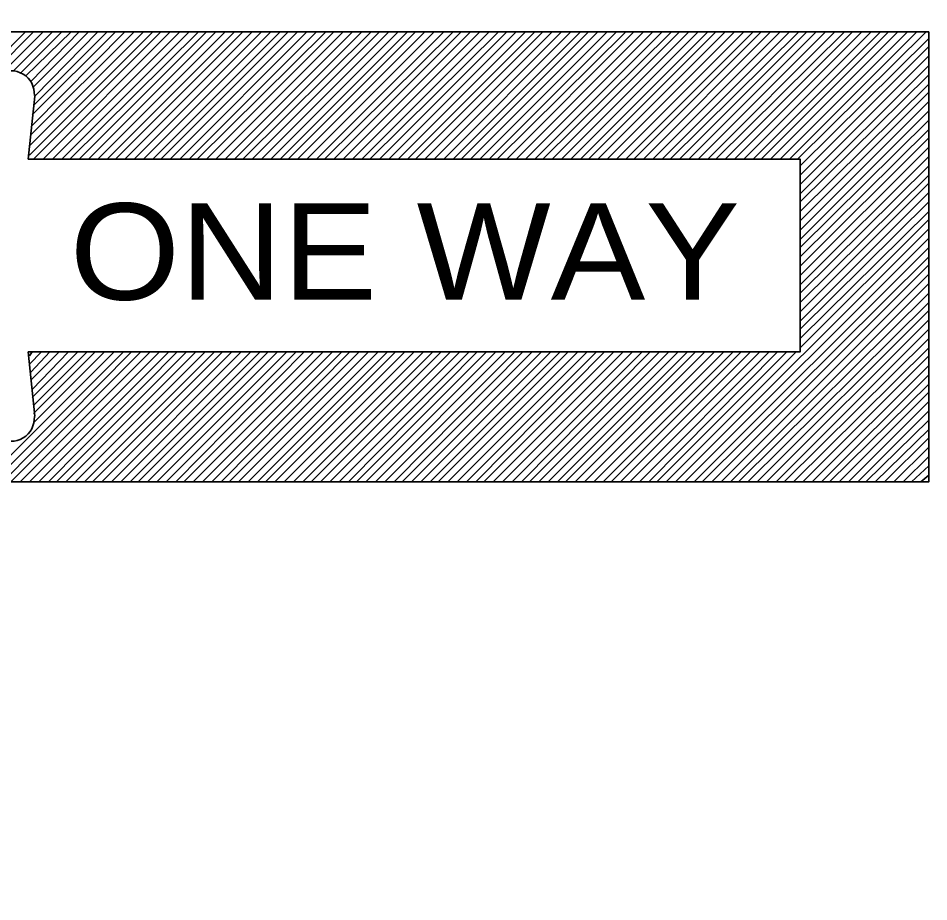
# Model space of a CAD drawing. Extents: x -198 to 658, y -402 to 142.
# Drawn here: x 497.03 to 513.34, y -95.51 to -79.68 of the extents above; entities that cross this region are included whole.
import ezdxf
from ezdxf.enums import TextEntityAlignment as Align

# ---------------------------------------------------------------- set-up
doc = ezdxf.new("R2010")
doc.units = 0
doc.header["$LTSCALE"] = 0.96
doc.layers.add('1', color=7, linetype='Continuous', lineweight=35)

msp = doc.modelspace()

# ---------------------------------------------------------------- linework, layer by layer
at = {"layer": '1'}
for p, q in [((491.4509, -85.6372), (497.1629, -79.9252)), ((491.4509, -85.8052), (497.3069, -79.9252)), ((491.4509, -85.6372), (497.1629, -79.9252)), ((491.4509, -85.8052), (497.3069, -79.9252)), ((496.7549, -80.6452), (497.4749, -79.9252)), ((496.7549, -80.6452), (497.4749, -79.9252)), ((496.9469, -80.6212), (497.6429, -79.9252)), ((496.9469, -80.6212), (497.6429, -79.9252)), ((497.0669, -80.6692), (497.8109, -79.9252)), ((497.0669, -80.6692), (497.8109, -79.9252)), ((497.1629, -80.7172), (497.9789, -79.9252)), ((497.1629, -80.7172), (497.9789, -79.9252)), ((497.2349, -81.9652), (499.2749, -79.9252)), ((497.2349, -82.1332), (499.4429, -79.9252)), ((497.2349, -81.9652), (499.2749, -79.9252)), ((497.2349, -82.1332), (499.4429, -79.9252)), ((497.2589, -80.8132), (498.1229, -79.9252)), ((497.2589, -81.7732), (499.1069, -79.9252)), ((497.2589, -80.8132), (498.1229, -79.9252)), ((497.2589, -81.7732), (499.1069, -79.9252)), ((497.2829, -81.4132), (498.7709, -79.9252)), ((497.2829, -81.6052), (498.9389, -79.9252)), ((497.2829, -81.4132), (498.7709, -79.9252)), ((497.2829, -81.6052), (498.9389, -79.9252)), ((497.3069, -80.9092), (498.2909, -79.9252)), ((497.3069, -81.2452), (498.6269, -79.9252)), ((497.3069, -82.2052), (499.5869, -79.9252)), ((497.3069, -80.9092), (498.2909, -79.9252)), ((497.3069, -81.2452), (498.6269, -79.9252)), ((497.3069, -82.2052), (499.5869, -79.9252)), ((497.3309, -81.0772), (498.4589, -79.9252)), ((497.3309, -81.0772), (498.4589, -79.9252)), ((497.4749, -82.2052), (499.7549, -79.9252)), ((497.4749, -82.2052), (499.7549, -79.9252)), ((497.6429, -82.2052), (499.9229, -79.9252)), ((497.6429, -82.2052), (499.9229, -79.9252)), ((497.8109, -82.2052), (500.0909, -79.9252)), ((497.8109, -82.2052), (500.0909, -79.9252)), ((497.9549, -82.2052), (500.2589, -79.9252)), ((497.9549, -82.2052), (500.2589, -79.9252)), ((498.1229, -82.2052), (500.4029, -79.9252)), ((498.1229, -82.2052), (500.4029, -79.9252)), ((498.2909, -82.2052), (500.5709, -79.9252)), ((498.2909, -82.2052), (500.5709, -79.9252)), ((498.4589, -82.2052), (500.7389, -79.9252)), ((498.4589, -82.2052), (500.7389, -79.9252)), ((498.6269, -82.2052), (500.9069, -79.9252)), ((498.6269, -82.2052), (500.9069, -79.9252)), ((498.7709, -82.2052), (501.0509, -79.9252)), ((498.7709, -82.2052), (501.0509, -79.9252)), ((498.9389, -82.2052), (501.2189, -79.9252)), ((498.9389, -82.2052), (501.2189, -79.9252)), ((499.1069, -82.2052), (501.3869, -79.9252)), ((499.1069, -82.2052), (501.3869, -79.9252)), ((499.2749, -82.2052), (501.5549, -79.9252)), ((499.2749, -82.2052), (501.5549, -79.9252)), ((499.4429, -82.2052), (501.7229, -79.9252)), ((499.4429, -82.2052), (501.7229, -79.9252)), ((499.5869, -82.2052), (501.8669, -79.9252)), ((499.5869, -82.2052), (501.8669, -79.9252)), ((499.7549, -82.2052), (502.0349, -79.9252)), ((499.7549, -82.2052), (502.0349, -79.9252)), ((499.9229, -82.2052), (502.2029, -79.9252)), ((499.9229, -82.2052), (502.2029, -79.9252)), ((500.0909, -82.2052), (502.3709, -79.9252)), ((500.0909, -82.2052), (502.3709, -79.9252)), ((500.2349, -82.2052), (502.5389, -79.9252)), ((500.2349, -82.2052), (502.5389, -79.9252)), ((500.4029, -82.2052), (502.6829, -79.9252)), ((500.4029, -82.2052), (502.6829, -79.9252)), ((500.5709, -82.2052), (502.8509, -79.9252)), ((500.5709, -82.2052), (502.8509, -79.9252)), ((500.7389, -82.2052), (503.0189, -79.9252)), ((500.7389, -82.2052), (503.0189, -79.9252)), ((500.9069, -82.2052), (503.1869, -79.9252)), ((500.9069, -82.2052), (503.1869, -79.9252)), ((501.0509, -82.2052), (503.3549, -79.9252)), ((501.0509, -82.2052), (503.3549, -79.9252)), ((501.2189, -82.2052), (503.4989, -79.9252)), ((501.2189, -82.2052), (503.4989, -79.9252)), ((501.3869, -82.2052), (503.6669, -79.9252)), ((501.3869, -82.2052), (503.6669, -79.9252)), ((501.5549, -82.2052), (503.8349, -79.9252)), ((501.5549, -82.2052), (503.8349, -79.9252)), ((501.7229, -82.2052), (504.0029, -79.9252)), ((501.7229, -82.2052), (504.0029, -79.9252)), ((501.8669, -82.2052), (504.1469, -79.9252)), ((501.8669, -82.2052), (504.1469, -79.9252)), ((502.0349, -82.2052), (504.3149, -79.9252)), ((502.0349, -82.2052), (504.3149, -79.9252)), ((502.2029, -82.2052), (504.4829, -79.9252)), ((502.2029, -82.2052), (504.4829, -79.9252)), ((502.3709, -82.2052), (504.6509, -79.9252)), ((502.3709, -82.2052), (504.6509, -79.9252)), ((502.5149, -82.2052), (504.8189, -79.9252)), ((502.5149, -82.2052), (504.8189, -79.9252)), ((502.6829, -82.2052), (504.9629, -79.9252)), ((502.6829, -82.2052), (504.9629, -79.9252)), ((502.8509, -82.2052), (505.1309, -79.9252)), ((502.8509, -82.2052), (505.1309, -79.9252)), ((503.0189, -82.2052), (505.2989, -79.9252)), ((503.0189, -82.2052), (505.2989, -79.9252)), ((503.1869, -82.2052), (505.4669, -79.9252)), ((503.1869, -82.2052), (505.4669, -79.9252)), ((503.3309, -82.2052), (505.6349, -79.9252)), ((503.3309, -82.2052), (505.6349, -79.9252)), ((503.4989, -82.2052), (505.7789, -79.9252)), ((503.4989, -82.2052), (505.7789, -79.9252)), ((503.6669, -82.2052), (505.9469, -79.9252)), ((503.6669, -82.2052), (505.9469, -79.9252)), ((503.8349, -82.2052), (506.1149, -79.9252)), ((503.8349, -82.2052), (506.1149, -79.9252)), ((504.0029, -82.2052), (506.2829, -79.9252)), ((504.0029, -82.2052), (506.2829, -79.9252)), ((504.1469, -82.2052), (506.4269, -79.9252)), ((504.1469, -82.2052), (506.4269, -79.9252)), ((504.3149, -82.2052), (506.5949, -79.9252)), ((504.3149, -82.2052), (506.5949, -79.9252)), ((504.4829, -82.2052), (506.7629, -79.9252)), ((504.4829, -82.2052), (506.7629, -79.9252)), ((504.6509, -82.2052), (506.9309, -79.9252)), ((504.6509, -82.2052), (506.9309, -79.9252)), ((504.8189, -82.2052), (507.0989, -79.9252)), ((504.8189, -82.2052), (507.0989, -79.9252)), ((504.9629, -82.2052), (507.2429, -79.9252)), ((504.9629, -82.2052), (507.2429, -79.9252)), ((505.1309, -82.2052), (507.4109, -79.9252)), ((505.1309, -82.2052), (507.4109, -79.9252)), ((505.2989, -82.2052), (507.5789, -79.9252)), ((505.2989, -82.2052), (507.5789, -79.9252)), ((505.4669, -82.2052), (507.7469, -79.9252)), ((505.4669, -82.2052), (507.7469, -79.9252)), ((505.6109, -82.2052), (507.9149, -79.9252)), ((505.6109, -82.2052), (507.9149, -79.9252)), ((505.7789, -82.2052), (508.0589, -79.9252)), ((505.7789, -82.2052), (508.0589, -79.9252)), ((505.9469, -82.2052), (508.2269, -79.9252)), ((505.9469, -82.2052), (508.2269, -79.9252)), ((506.1149, -82.2052), (508.3949, -79.9252)), ((506.1149, -82.2052), (508.3949, -79.9252)), ((506.2829, -82.2052), (508.5629, -79.9252)), ((506.2829, -82.2052), (508.5629, -79.9252)), ((506.4269, -82.2052), (508.7309, -79.9252)), ((506.4269, -82.2052), (508.7309, -79.9252)), ((506.5949, -82.2052), (508.8749, -79.9252)), ((506.5949, -82.2052), (508.8749, -79.9252)), ((506.7629, -82.2052), (509.0429, -79.9252)), ((506.7629, -82.2052), (509.0429, -79.9252)), ((506.9309, -82.2052), (509.2109, -79.9252)), ((506.9309, -82.2052), (509.2109, -79.9252)), ((507.0989, -82.2052), (509.3789, -79.9252)), ((507.0989, -82.2052), (509.3789, -79.9252)), ((507.2429, -82.2052), (509.5229, -79.9252)), ((507.2429, -82.2052), (509.5229, -79.9252)), ((507.4109, -82.2052), (509.6909, -79.9252)), ((507.4109, -82.2052), (509.6909, -79.9252)), ((507.5789, -82.2052), (509.8589, -79.9252)), ((507.5789, -82.2052), (509.8589, -79.9252)), ((507.7469, -82.2052), (510.0269, -79.9252)), ((507.7469, -82.2052), (510.0269, -79.9252)), ((507.9149, -82.2052), (510.1949, -79.9252)), ((507.9149, -82.2052), (510.1949, -79.9252)), ((508.0589, -82.2052), (510.3389, -79.9252)), ((508.0589, -82.2052), (510.3389, -79.9252)), ((508.2269, -82.2052), (510.5069, -79.9252)), ((508.2269, -82.2052), (510.5069, -79.9252)), ((508.3949, -82.2052), (510.6749, -79.9252)), ((508.3949, -82.2052), (510.6749, -79.9252)), ((508.5629, -82.2052), (510.8429, -79.9252)), ((508.5629, -82.2052), (510.8429, -79.9252)), ((508.7069, -82.2052), (511.0109, -79.9252)), ((508.7069, -82.2052), (511.0109, -79.9252)), ((508.8749, -82.2052), (511.1549, -79.9252)), ((508.8749, -82.2052), (511.1549, -79.9252)), ((509.0429, -82.2052), (511.3229, -79.9252)), ((509.0429, -82.2052), (511.3229, -79.9252)), ((509.2109, -82.2052), (511.4909, -79.9252)), ((509.2109, -82.2052), (511.4909, -79.9252)), ((509.3789, -82.2052), (511.6589, -79.9252)), ((509.3789, -82.2052), (511.6589, -79.9252)), ((509.5229, -82.2052), (511.8269, -79.9252)), ((509.5229, -82.2052), (511.8269, -79.9252)), ((509.6909, -82.2052), (511.9709, -79.9252)), ((509.6909, -82.2052), (511.9709, -79.9252)), ((509.8589, -82.2052), (512.1389, -79.9252)), ((509.8589, -82.2052), (512.1389, -79.9252)), ((510.0269, -82.2052), (512.3069, -79.9252)), ((510.0269, -82.2052), (512.3069, -79.9252)), ((510.1949, -82.2052), (512.4749, -79.9252)), ((510.1949, -82.2052), (512.4749, -79.9252)), ((510.3389, -82.2052), (512.6189, -79.9252)), ((510.3389, -82.2052), (512.6189, -79.9252)), ((510.5069, -82.2052), (512.7869, -79.9252)), ((510.5069, -82.2052), (512.7869, -79.9252)), ((510.6749, -82.2052), (512.9549, -79.9252)), ((510.6749, -82.2052), (512.9549, -79.9252)), ((510.8429, -82.2052), (513.1229, -79.9252)), ((510.8429, -82.2052), (513.1229, -79.9252)), ((510.9869, -82.2052), (513.2909, -79.9252)), ((510.9869, -82.2052), (513.2909, -79.9252)), ((511.0349, -82.3252), (513.3389, -80.0452)), ((511.0349, -82.3252), (513.3389, -80.0452)), ((511.0349, -82.4932), (513.3389, -80.1892)), ((511.0349, -82.4932), (513.3389, -80.1892)), ((511.0349, -82.6612), (513.3389, -80.3572)), ((511.0349, -82.6612), (513.3389, -80.3572)), ((511.0349, -82.8292), (513.3389, -80.5252)), ((511.0349, -82.8292), (513.3389, -80.5252)), ((511.0349, -82.9732), (513.3389, -80.6932)), ((511.0349, -82.9732), (513.3389, -80.6932)), ((511.0349, -83.1412), (513.3389, -80.8612)), ((511.0349, -83.1412), (513.3389, -80.8612)), ((511.0349, -83.3092), (513.3389, -81.0052)), ((511.0349, -83.3092), (513.3389, -81.0052)), ((511.0349, -83.4772), (513.3389, -81.1732)), ((511.0349, -83.4772), (513.3389, -81.1732)), ((511.0349, -83.6452), (513.3389, -81.3412)), ((511.0349, -83.6452), (513.3389, -81.3412)), ((511.0349, -83.7892), (513.3389, -81.5092)), ((511.0349, -83.7892), (513.3389, -81.5092)), ((511.0349, -83.9572), (513.3389, -81.6772)), ((511.0349, -83.9572), (513.3389, -81.6772)), ((511.0349, -84.1252), (513.3389, -81.8212)), ((511.0349, -84.1252), (513.3389, -81.8212)), ((511.0349, -84.2932), (513.3389, -81.9892)), ((511.0349, -84.2932), (513.3389, -81.9892)), ((511.0349, -84.4612), (513.3389, -82.1572)), ((511.0349, -84.4612), (513.3389, -82.1572)), ((511.0349, -84.6052), (513.3389, -82.3252)), ((511.0349, -84.6052), (513.3389, -82.3252)), ((511.0349, -84.7732), (513.3389, -82.4932)), ((511.0349, -84.7732), (513.3389, -82.4932)), ((511.0349, -84.9412), (513.3389, -82.6372)), ((511.0349, -84.9412), (513.3389, -82.6372)), ((511.0349, -85.1092), (513.3389, -82.8052)), ((511.0349, -85.1092), (513.3389, -82.8052)), ((511.0349, -85.2532), (513.3389, -82.9732)), ((511.0349, -85.2532), (513.3389, -82.9732)), ((511.0349, -85.4212), (513.3389, -83.1412)), ((511.0349, -85.4212), (513.3389, -83.1412)), ((511.0349, -85.5892), (513.3389, -83.2852)), ((511.0349, -85.5892), (513.3389, -83.2852)), ((508.8029, -87.9892), (513.3389, -83.4532)), ((508.8029, -87.9892), (513.3389, -83.4532)), ((508.9709, -87.9892), (513.3389, -83.6212)), ((508.9709, -87.9892), (513.3389, -83.6212)), ((509.1389, -87.9892), (513.3389, -83.7892)), ((509.1389, -87.9892), (513.3389, -83.7892)), ((509.2829, -87.9892), (513.3389, -83.9572)), ((509.2829, -87.9892), (513.3389, -83.9572)), ((509.4509, -87.9892), (513.3389, -84.1012)), ((509.4509, -87.9892), (513.3389, -84.1012)), ((509.6189, -87.9892), (513.3389, -84.2692)), ((509.6189, -87.9892), (513.3389, -84.2692)), ((509.7869, -87.9892), (513.3389, -84.4372)), ((509.7869, -87.9892), (513.3389, -84.4372)), ((509.9309, -87.9892), (513.3389, -84.6052)), ((509.9309, -87.9892), (513.3389, -84.6052)), ((510.0989, -87.9892), (513.3389, -84.7732)), ((510.0989, -87.9892), (513.3389, -84.7732)), ((510.2669, -87.9892), (513.3389, -84.9172)), ((510.2669, -87.9892), (513.3389, -84.9172)), ((510.4349, -87.9892), (513.3389, -85.0852)), ((510.4349, -87.9892), (513.3389, -85.0852)), ((510.6029, -87.9892), (513.3389, -85.2532)), ((510.6029, -87.9892), (513.3389, -85.2532)), ((510.7469, -87.9892), (513.3389, -85.4212)), ((510.7469, -87.9892), (513.3389, -85.4212)), ((510.9149, -87.9892), (513.3389, -85.5892)), ((510.9149, -87.9892), (513.3389, -85.5892)), ((496.4189, -87.9892), (498.7469, -85.6612)), ((496.4189, -87.9892), (498.7469, -85.6612)), ((496.5869, -87.9892), (498.9149, -85.6612)), ((496.5869, -87.9892), (498.9149, -85.6612)), ((496.7549, -87.9892), (499.0589, -85.6612)), ((496.7549, -87.9892), (499.0589, -85.6612)), ((496.8989, -87.9892), (499.2269, -85.6612)), ((496.8989, -87.9892), (499.2269, -85.6612)), ((497.0669, -87.9892), (499.3949, -85.6612)), ((497.0669, -87.9892), (499.3949, -85.6612)), ((497.2349, -85.7332), (497.2829, -85.6612)), ((497.2349, -85.8772), (497.4509, -85.6612)), ((497.2349, -87.9892), (499.5629, -85.6612)), ((497.2349, -85.7332), (497.2829, -85.6612)), ((497.2349, -85.8772), (497.4509, -85.6612)), ((497.2349, -87.9892), (499.5629, -85.6612)), ((497.2589, -86.0212), (497.5949, -85.6612)), ((497.2589, -86.1652), (497.7629, -85.6612)), ((497.2589, -86.0212), (497.5949, -85.6612)), ((497.2589, -86.1652), (497.7629, -85.6612)), ((497.2829, -86.3332), (497.9309, -85.6612)), ((497.2829, -86.4772), (498.0989, -85.6612)), ((497.2829, -86.3332), (497.9309, -85.6612)), ((497.2829, -86.4772), (498.0989, -85.6612)), ((497.3069, -86.6212), (498.2669, -85.6612)), ((497.3069, -86.7652), (498.4109, -85.6612)), ((497.3069, -86.9332), (498.5789, -85.6612)), ((497.3069, -86.6212), (498.2669, -85.6612)), ((497.3069, -86.7652), (498.4109, -85.6612)), ((497.3069, -86.9332), (498.5789, -85.6612)), ((497.4029, -87.9892), (499.7309, -85.6612)), ((497.4029, -87.9892), (499.7309, -85.6612)), ((497.5709, -87.9892), (499.8749, -85.6612)), ((497.5709, -87.9892), (499.8749, -85.6612)), ((497.7149, -87.9892), (500.0429, -85.6612)), ((497.7149, -87.9892), (500.0429, -85.6612)), ((497.8829, -87.9892), (500.2109, -85.6612)), ((497.8829, -87.9892), (500.2109, -85.6612)), ((498.0509, -87.9892), (500.3789, -85.6612)), ((498.0509, -87.9892), (500.3789, -85.6612)), ((498.2189, -87.9892), (500.5469, -85.6612)), ((498.2189, -87.9892), (500.5469, -85.6612)), ((498.3629, -87.9892), (500.6909, -85.6612)), ((498.3629, -87.9892), (500.6909, -85.6612)), ((498.5309, -87.9892), (500.8589, -85.6612)), ((498.5309, -87.9892), (500.8589, -85.6612)), ((498.6989, -87.9892), (501.0269, -85.6612)), ((498.6989, -87.9892), (501.0269, -85.6612)), ((498.8669, -87.9892), (501.1949, -85.6612)), ((498.8669, -87.9892), (501.1949, -85.6612)), ((499.0349, -87.9892), (501.3629, -85.6612)), ((499.0349, -87.9892), (501.3629, -85.6612)), ((499.1789, -87.9892), (501.5069, -85.6612)), ((499.1789, -87.9892), (501.5069, -85.6612)), ((499.3469, -87.9892), (501.6749, -85.6612)), ((499.3469, -87.9892), (501.6749, -85.6612)), ((499.5149, -87.9892), (501.8429, -85.6612)), ((499.5149, -87.9892), (501.8429, -85.6612)), ((499.6829, -87.9892), (502.0109, -85.6612)), ((499.6829, -87.9892), (502.0109, -85.6612)), ((499.8509, -87.9892), (502.1549, -85.6612)), ((499.8509, -87.9892), (502.1549, -85.6612)), ((499.9949, -87.9892), (502.3229, -85.6612)), ((499.9949, -87.9892), (502.3229, -85.6612)), ((500.1629, -87.9892), (502.4909, -85.6612)), ((500.1629, -87.9892), (502.4909, -85.6612)), ((500.3309, -87.9892), (502.6589, -85.6612)), ((500.3309, -87.9892), (502.6589, -85.6612)), ((500.4989, -87.9892), (502.8269, -85.6612)), ((500.4989, -87.9892), (502.8269, -85.6612)), ((500.6669, -87.9892), (502.9709, -85.6612)), ((500.6669, -87.9892), (502.9709, -85.6612)), ((500.8109, -87.9892), (503.1389, -85.6612)), ((500.8109, -87.9892), (503.1389, -85.6612)), ((500.9789, -87.9892), (503.3069, -85.6612)), ((500.9789, -87.9892), (503.3069, -85.6612)), ((501.1469, -87.9892), (503.4749, -85.6612)), ((501.1469, -87.9892), (503.4749, -85.6612)), ((501.3149, -87.9892), (503.6429, -85.6612)), ((501.3149, -87.9892), (503.6429, -85.6612)), ((501.4589, -87.9892), (503.7869, -85.6612)), ((501.4589, -87.9892), (503.7869, -85.6612)), ((501.6269, -87.9892), (503.9549, -85.6612)), ((501.6269, -87.9892), (503.9549, -85.6612)), ((501.7949, -87.9892), (504.1229, -85.6612)), ((501.7949, -87.9892), (504.1229, -85.6612)), ((501.9629, -87.9892), (504.2909, -85.6612)), ((501.9629, -87.9892), (504.2909, -85.6612)), ((502.1309, -87.9892), (504.4589, -85.6612)), ((502.1309, -87.9892), (504.4589, -85.6612)), ((502.2749, -87.9892), (504.6029, -85.6612)), ((502.2749, -87.9892), (504.6029, -85.6612)), ((502.4429, -87.9892), (504.7709, -85.6612)), ((502.4429, -87.9892), (504.7709, -85.6612)), ((502.6109, -87.9892), (504.9389, -85.6612)), ((502.6109, -87.9892), (504.9389, -85.6612)), ((502.7789, -87.9892), (505.1069, -85.6612)), ((502.7789, -87.9892), (505.1069, -85.6612)), ((502.9469, -87.9892), (505.2509, -85.6612)), ((502.9469, -87.9892), (505.2509, -85.6612)), ((503.0909, -87.9892), (505.4189, -85.6612)), ((503.0909, -87.9892), (505.4189, -85.6612)), ((503.2589, -87.9892), (505.5869, -85.6612)), ((503.2589, -87.9892), (505.5869, -85.6612)), ((503.4269, -87.9892), (505.7549, -85.6612)), ((503.4269, -87.9892), (505.7549, -85.6612)), ((503.5949, -87.9892), (505.9229, -85.6612)), ((503.5949, -87.9892), (505.9229, -85.6612)), ((503.7629, -87.9892), (506.0669, -85.6612)), ((503.7629, -87.9892), (506.0669, -85.6612)), ((503.9069, -87.9892), (506.2349, -85.6612)), ((503.9069, -87.9892), (506.2349, -85.6612)), ((504.0749, -87.9892), (506.4029, -85.6612)), ((504.0749, -87.9892), (506.4029, -85.6612)), ((504.2429, -87.9892), (506.5709, -85.6612)), ((504.2429, -87.9892), (506.5709, -85.6612)), ((504.4109, -87.9892), (506.7389, -85.6612)), ((504.4109, -87.9892), (506.7389, -85.6612)), ((504.5549, -87.9892), (506.8829, -85.6612)), ((504.5549, -87.9892), (506.8829, -85.6612)), ((504.7229, -87.9892), (507.0509, -85.6612)), ((504.7229, -87.9892), (507.0509, -85.6612)), ((504.8909, -87.9892), (507.2189, -85.6612)), ((504.8909, -87.9892), (507.2189, -85.6612)), ((505.0589, -87.9892), (507.3869, -85.6612)), ((505.0589, -87.9892), (507.3869, -85.6612)), ((505.2269, -87.9892), (507.5309, -85.6612)), ((505.2269, -87.9892), (507.5309, -85.6612)), ((505.3709, -87.9892), (507.6989, -85.6612)), ((505.3709, -87.9892), (507.6989, -85.6612)), ((505.5389, -87.9892), (507.8669, -85.6612)), ((505.5389, -87.9892), (507.8669, -85.6612)), ((505.7069, -87.9892), (508.0349, -85.6612)), ((505.7069, -87.9892), (508.0349, -85.6612)), ((505.8749, -87.9892), (508.2029, -85.6612)), ((505.8749, -87.9892), (508.2029, -85.6612)), ((506.0429, -87.9892), (508.3469, -85.6612)), ((506.0429, -87.9892), (508.3469, -85.6612)), ((506.1869, -87.9892), (508.5149, -85.6612)), ((506.1869, -87.9892), (508.5149, -85.6612)), ((506.3549, -87.9892), (508.6829, -85.6612)), ((506.3549, -87.9892), (508.6829, -85.6612)), ((506.5229, -87.9892), (508.8509, -85.6612)), ((506.5229, -87.9892), (508.8509, -85.6612)), ((506.6909, -87.9892), (509.0189, -85.6612)), ((506.6909, -87.9892), (509.0189, -85.6612)), ((506.8349, -87.9892), (509.1629, -85.6612)), ((506.8349, -87.9892), (509.1629, -85.6612)), ((507.0029, -87.9892), (509.3309, -85.6612)), ((507.0029, -87.9892), (509.3309, -85.6612)), ((507.1709, -87.9892), (509.4989, -85.6612)), ((507.1709, -87.9892), (509.4989, -85.6612)), ((507.3389, -87.9892), (509.6669, -85.6612)), ((507.3389, -87.9892), (509.6669, -85.6612)), ((507.5069, -87.9892), (509.8349, -85.6612)), ((507.5069, -87.9892), (509.8349, -85.6612)), ((507.6509, -87.9892), (509.9789, -85.6612)), ((507.6509, -87.9892), (509.9789, -85.6612)), ((507.8189, -87.9892), (510.1469, -85.6612)), ((507.8189, -87.9892), (510.1469, -85.6612)), ((507.9869, -87.9892), (510.3149, -85.6612)), ((507.9869, -87.9892), (510.3149, -85.6612)), ((508.1549, -87.9892), (510.4829, -85.6612)), ((508.1549, -87.9892), (510.4829, -85.6612)), ((508.3229, -87.9892), (510.6269, -85.6612)), ((508.3229, -87.9892), (510.6269, -85.6612)), ((508.4669, -87.9892), (510.7949, -85.6612)), ((508.4669, -87.9892), (510.7949, -85.6612)), ((508.6349, -87.9892), (510.9629, -85.6612)), ((508.6349, -87.9892), (510.9629, -85.6612)), ((511.0829, -87.9892), (513.3389, -85.7332)), ((511.0829, -87.9892), (513.3389, -85.7332)), ((511.2509, -87.9892), (513.3389, -85.9012)), ((511.2509, -87.9892), (513.3389, -85.9012)), ((511.4189, -87.9892), (513.3389, -86.0692)), ((511.4189, -87.9892), (513.3389, -86.0692)), ((511.5629, -87.9892), (513.3389, -86.2372)), ((511.5629, -87.9892), (513.3389, -86.2372)), ((511.7309, -87.9892), (513.3389, -86.3812)), ((511.7309, -87.9892), (513.3389, -86.3812)), ((511.8989, -87.9892), (513.3389, -86.5492)), ((511.8989, -87.9892), (513.3389, -86.5492)), ((512.0669, -87.9892), (513.3389, -86.7172)), ((512.0669, -87.9892), (513.3389, -86.7172)), ((512.2109, -87.9892), (513.3389, -86.8852)), ((512.2109, -87.9892), (513.3389, -86.8852)), ((512.3789, -87.9892), (513.3389, -87.0532)), ((512.3789, -87.9892), (513.3389, -87.0532)), ((512.5469, -87.9892), (513.3389, -87.1972)), ((512.5469, -87.9892), (513.3389, -87.1972)), ((512.7149, -87.9892), (513.3389, -87.3652)), ((512.7149, -87.9892), (513.3389, -87.3652)), ((512.8829, -87.9892), (513.3389, -87.5332)), ((512.8829, -87.9892), (513.3389, -87.5332)), ((513.0269, -87.9892), (513.3389, -87.7012)), ((513.0269, -87.9892), (513.3389, -87.7012)), ((513.1949, -87.9892), (513.3389, -87.8692)), ((513.1949, -87.9892), (513.3389, -87.8692))]:
    msp.add_line(p, q, dxfattribs=at)
msp.add_lwpolyline([(491.4509, -79.9252), (513.3389, -79.9252), (513.3389, -87.9892), (491.4509, -87.9892)], close=True, dxfattribs=at)
msp.add_lwpolyline([(491.4509, -79.9252), (513.3389, -79.9252), (513.3389, -87.9892), (491.4509, -87.9892)], close=True, dxfattribs=at)
msp.add_lwpolyline([(497.3309, -81.0772), (497.2109, -82.2052), (511.0349, -82.2052), (511.0349, -85.6612), (497.2109, -85.6612), (497.3309, -86.8132)], dxfattribs=at)
msp.add_lwpolyline([(497.3309, -81.0772), (497.2109, -82.2052), (511.0349, -82.2052), (511.0349, -85.6612), (497.2109, -85.6612), (497.3309, -86.8132)], dxfattribs=at)
at = {"layer": '1', "lineweight": 53}
msp.add_arc((506.207, -91.0305), 36.6668, 89.84467, 191.96498, dxfattribs=at)
at = {"layer": '1'}
for centre, start, end in [((496.9017, -81.0416), 356.63551, 121.23355), ((496.9017, -81.0416), 356.63551, 121.23355), ((496.9017, -86.8419), 238.76645, 3.36449), ((496.9017, -86.8419), 238.76645, 3.36449)]:
    msp.add_arc(centre, 0.419, start, end, dxfattribs=at)

# ---------------------------------------------------------------- texts
at = {"layer": '1', "width": 1.1}
for p in [(503.9549, -84.7252), (503.9553, -84.7252)]:
    msp.add_text('ONE WAY', height=1.728, dxfattribs=at).set_placement(p, align=Align.CENTER)

doc.saveas('drawing.dxf')
